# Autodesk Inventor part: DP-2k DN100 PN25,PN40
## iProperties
Created: 2009-08
Part Number: DP-2k DN100 PN25,PN40
Document SubType Name: Modelowanie
Designer: Marcin Pyzik
Author: Marcin Pyzik
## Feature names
1. Wyciągnięcie proste1 [Extrusion]
2. Faza1 [Chamfer]
3. Faza2 [Chamfer]
4. Bryła wyprowadzona1 [Tagging]
5. Wyciągnięcie proste2 [Extrusion]
